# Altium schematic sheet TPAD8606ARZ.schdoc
size 127 x 101 mm
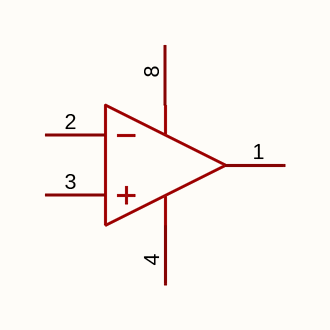
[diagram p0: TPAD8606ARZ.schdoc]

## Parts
U?  tpad8606arz  [SOIC-8_L5.0-W4.0-P1.27-LS6.0-BL]  (value not drawn)  (part A of 2)

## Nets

Not connected (* = marked no-connect by the designer): U? 1(OUT1) 2(IN1-) 3(IN1+) 4(VEE) 8(VCC)

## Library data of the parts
U? = tpad8606arz: 放大器数:2;轨到轨:轨到轨输入,轨到轨输出;增益带宽积(GBW):10MHz;输入失调电压(Vos):5mV;压摆率(SR):4.5V/us;输入偏置电流(Ib):1pA;; Manufacturer: TECH PUBLIC(台舟); AddInBom: yes; ModelId: 7abc64c95a1a4a04a4ef38f9097c870b; ModelTransform: 192.913,236.22,0,0,0,0,0,0,0; Number of Channels: 2; Gain Bandwidth Product: 10MHz; Vos - Input Offset Voltage: 5mV; Input Offset Voltage Drift(Vos TC): 300nV/℃; Ib - Input Bias Current: 1pA; Input Offset Current(Ios): 100pA; Input Voltage Noise Density: 15nV/√Hz@1kHz; Common Mode Rejection Ratio(CMRR): 75dB; Quiescent Current: 1.6mA; Output Current: 50mA; Single supply: 2.2V~5.5V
